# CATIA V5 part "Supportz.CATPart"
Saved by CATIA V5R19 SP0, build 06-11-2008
Part number: Supportz
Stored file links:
  G:\EU_thinkMotion\CFAO_2010\MMS_groupe3\MMS_groupe3\A reprendre\evulliez\evulliez\Supportz.CATPart

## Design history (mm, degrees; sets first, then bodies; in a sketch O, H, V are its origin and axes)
Body1 (main body)
  Point1: (0, 0, 0)
  Line1: type PtDir, RefPoint Point1, Direction (0, 0, 1), Start -50, End 500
